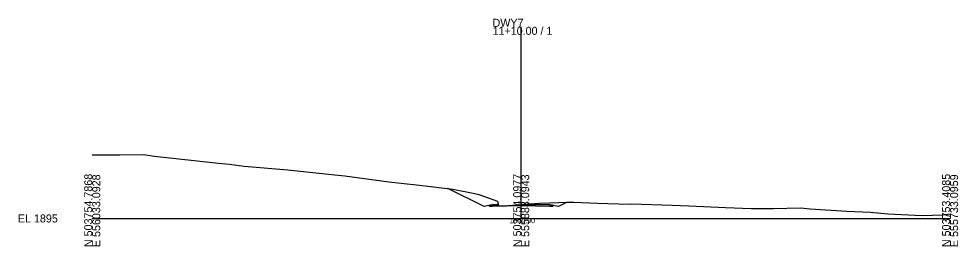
# Model space of a CAD drawing. Extents: x -26 to 1503, y -10 to 1052.
# Drawn here: x 1174.3 to 1502.8, y 490.3 to 569.8 of the extents above; entities that cross this region are included whole.
import ezdxf

# ---------------------------------------------------------------- set-up
doc = ezdxf.new("R2010")
doc.units = 0
for name, color, linetype in [('Exist Cross Section Cell', 7, 'Continuous'), ('Exist XS Ground Line', 7, 'Continuous'), ('Prop XS Ditch Standard Text', 7, 'Continuous'), ('Prop XS Earthwork Shape', 7, 'Continuous')]:
    doc.layers.add(name, color=color, linetype=linetype)

msp = doc.modelspace()

# ---------------------------------------------------------------- linework, layer by layer
at = {"layer": 'Exist Cross Section Cell'}
for p, q in [((1350, 500), (1350, 566.98)), ((1200, 500), (1350, 500)), ((1350, 500), (1500, 500))]:
    msp.add_line(p, q, dxfattribs=at)
at = {"layer": 'Exist XS Ground Line'}
msp.add_lwpolyline([(1200, 522.23), (1206.43, 522.19), (1209.6, 522.25), (1217.92, 522.33), (1221.79, 521.77), (1244.2, 519.32), (1248.02, 518.95), (1253.08, 518.31), (1268.43, 517.02), (1283.61, 515.34), (1288.28, 514.89), (1303.67, 512.85), (1308.02, 512.36), (1314.39, 511.59), (1326.07, 510.25), (1333.79, 508.69), (1335.15, 508.38), (1337.18, 507.62), (1341.69, 506.02), (1342.03, 504.51), (1343.84, 504.36), (1350, 504.9), (1350.68, 504.96), (1352.06, 505.08), (1352.87, 505.15), (1356.28, 505.3), (1360.02, 505.46), (1366.27, 505.7), (1367.09, 505.69), (1368.45, 505.64), (1376.52, 505.31), (1387.92, 505.04), (1388.41, 505.08), (1402.84, 504.64), (1408.61, 504.41), (1421.41, 503.88), (1430.49, 503.54), (1438.29, 503.45), (1447.71, 503.75), (1451.07, 503.31), (1463.92, 502.6), (1472.12, 502.18), (1478.23, 501.63), (1490.25, 501.02), (1497.42, 501.3), (1500, 501.65)], dxfattribs=at)
at = {"layer": 'Prop XS Earthwork Shape'}
for points in [[(1338.66, 504.55), (1337, 504.14), (1324.4, 510.44), (1326.07, 510.25), (1333.79, 508.69), (1335.15, 508.38), (1337.18, 507.62), (1341.69, 506.02), (1341.97, 504.76), (1340, 504.72), (1339, 504.64)], [(1360, 504.72), (1361, 504.64), (1361.34, 504.55), (1361, 504.21), (1360, 504.22), (1350, 504.42), (1340, 504.22), (1339, 504.21), (1338.66, 504.55), (1339, 504.64), (1340, 504.72), (1341.97, 504.76), (1342.03, 504.51), (1343.84, 504.36), (1350, 504.92)], [(1360.02, 505.46), (1366.1, 505.69), (1363, 504.14), (1361.34, 504.55), (1361, 504.64), (1360, 504.72), (1350, 504.92), (1350.68, 504.96), (1352.06, 505.08), (1352.87, 505.15), (1356.28, 505.3)]]:
    msp.add_lwpolyline(points, close=True, dxfattribs=at)

# ---------------------------------------------------------------- texts
at = {"layer": 'Exist Cross Section Cell'}
for s, p in [('DWY7', (1340, 566.98)), ('11+10.00 / 1', (1340, 564.18)), ('EL 1895', (1174, 498.6))]:
    msp.add_text(s, height=2.8, dxfattribs=at).set_placement(p)
for s, p in [('N 503754.7868', (1200, 490)), ('E 556033.0928', (1202.8, 490)), ('N 503754.0977', (1350, 490)), ('E 555883.0943', (1352.8, 490)), ('N 503753.4085', (1500, 490)), ('E 555733.0959', (1502.8, 490))]:
    msp.add_text(s, height=2.8, rotation=90, dxfattribs=at).set_placement(p)
at = {"layer": 'Prop XS Ditch Standard Text'}
msp.add_text('1899.90', height=1.8, dxfattribs=at).set_placement((1345.88, 498.35))

doc.saveas('drawing.dxf')
